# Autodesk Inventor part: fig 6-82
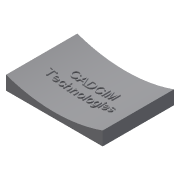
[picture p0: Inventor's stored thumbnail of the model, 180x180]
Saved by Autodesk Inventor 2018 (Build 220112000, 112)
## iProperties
Shininess: 64.0
Length Units: 11269
Angle Units: 11279
Time Units: 11290
Mass Units: 11283
Length Display Precision: 3
Angle Display Precision: 2
Compacted: True
Part Number: fig 6-82
Document SubType Name: Modeling
Created: 2002-12
Designer: deepak
Density: 1 g/cm^3
Material: Generic
Appearance: Default
Density: 0.0
Volumn: 0.0
Area: 0.0
PropertySet Name: Model Information
Control State: 0
Master: False
Checked Out: False
Author: deepak
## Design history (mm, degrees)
sketch "Sketch1"
  geometry: L1 (-39.922, 33.786)-(30.103, 33.786); L2 (30.103, 33.786)-(30.103, -17.894); L3 (30.103, -17.894)-(-39.922, -17.894); L4 (-39.922, -17.894)-(-39.922, 33.786)
  constraints: 8 end point, 2 parallel, 1 horizontal, 1 perpendicular
extrude "Extrusion1" new body sketch "Sketch1" distance "d0" = 10; taper "d1" = 0 deg
workplane "Work Plane1"
sketch "Sketch2"
  geometry: L1 (-37.656, 15.034)-(26.28, 15.034); L2 (26.28, 15.034)-(26.28, 10.168); L3 (26.28, 10.168)-(-37.656, 10.168); L4 (-37.656, 10.168)-(-37.656, 15.034)
  constraints: 2 other
sketch "Sketch3"
  geometry: L1 (70.026, 10)-(0, 10) reference; A1 r 105 centre (35.013, 108.99) between (0, 10) and (70.026, 10)
  constraints: 2 point on circle, 1 centre point
  dimensions: "d5" = 105 radius of A1
extrude "Extrusion2" cut sketch "Sketch3" extent not by distance; stored distance "d3" = 10; taper "d4" = 0 deg
emboss "Emboss4" sketch "Sketch2" dims "d14" = 1, "d15" = 0
body "Solid1"
other parameters: "d2" = 5
